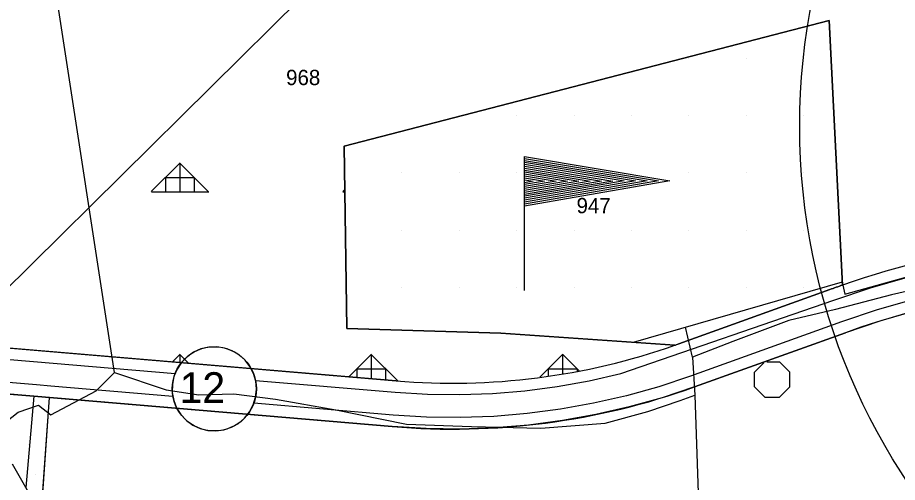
# Model space of a CAD drawing. Extents: x 410727 to 412947, y 4463506 to 4466382.
# Drawn here: x 411101.3 to 411331.1, y 4465660.4 to 4465781.8 of the extents above; entities that cross this region are included whole.
import ezdxf

# ---------------------------------------------------------------- set-up
doc = ezdxf.new("R2010")
doc.units = 0
for name, color, linetype in [('ADAKENARI', 7, 'Continuous'), ('KALDIRIM', 7, 'Continuous'), ('KDS_PARSEL_NO', 7, 'Continuous'), ('KDS_PL', 7, 'Continuous'), ('LJ_SEMBOL', 7, 'Continuous'), ('LJ_ÇERÇEVE', 7, 'Continuous'), ('PL_AYA_ORMAN', 7, 'Continuous'), ('PL_AYA_PARK_DINLENME', 7, 'Continuous'), ('PL_KA_TARIM_DIGER', 7, 'Continuous'), ('PL_SPOR', 7, 'Continuous'), ('sm_yol_beyaz', 7, 'Continuous'), ('sm_yol_genisligi', 7, 'Continuous'), ('TR_ORMAN', 7, 'Continuous'), ('TR_PARKALANI', 7, 'Continuous'), ('TR_SPOR', 7, 'Continuous'), ('TR_TARIMALANI', 7, 'Continuous'), ('Yerlesime_uygunluk_sınırı', 7, 'Continuous')]:
    doc.layers.add(name, color=color, linetype=linetype)

msp = doc.modelspace()

# ---------------------------------------------------------------- linework, layer by layer
at = {"layer": 'ADAKENARI'}
for p, q in [((411313.23, 4465781.05), (411186.63, 4465748.25)), ((411313.23, 4465781.05), (411316.74, 4465711.91)), ((411186.63, 4465748.25), (411187.26, 4465700.58)), ((411313.48, 4465710.76), (411274.04, 4465696.59)), ((411200.14, 4465686.91), (411040.78, 4465700.4)), ((411187.26, 4465700.58), (411227.54, 4465699.31)), ((411227.54, 4465699.31), (411272.97, 4465696.21)), ((411278.1, 4465685.3), (411317.54, 4465699.47)), ((411063.08, 4465686.47), (411105.53, 4465682.88)), ((411105.53, 4465682.88), (411109.68, 4465682.53)), ((411106.96, 4465644.62), (411109.68, 4465682.53)), ((411109.68, 4465682.53), (411199.13, 4465674.95))]:
    msp.add_line(p, q, dxfattribs=at)
for centre, radius, start, end in [((411398.47, 4465474.33), 251.25, 87.2905, 108.9831), ((411398.47, 4465474.33), 239.25, 77.2133, 109.7719), ((411398.47, 4465474.33), 251.25, 108.9831, 109.7719), ((411214.9, 4465861.12), 174.84, 289.3989, 289.7719), ((411214.9, 4465861.12), 174.84, 265.1582, 289.3989), ((411214.9, 4465861.12), 186.84, 265.1582, 289.7719)]:
    msp.add_arc(centre, radius, start, end, dxfattribs=at)
at = {"layer": 'KALDIRIM'}
msp.add_line((411258.83, 4465688.79), (411314.49, 4465707.94), dxfattribs=at)
for points in [[(411314.49, 4465707.94), (411324.04, 4465711.16), (411333.71, 4465713.98)], [(411335.28, 4465708.19), (411325.84, 4465705.43), (411316.52, 4465702.29), (411277.09, 4465688.12), (411268.76, 4465685.35), (411260.31, 4465682.98), (411251.76, 4465681.02), (411243.12, 4465679.46), (411234.43, 4465678.32), (411225.68, 4465677.6), (411216.91, 4465677.29), (411208.14, 4465677.41), (411199.38, 4465677.94), (411163.01, 4465681.02)], [(410789.95, 4465702), (410815.7, 4465699.61), (410852.1, 4465692.73), (410854.34, 4465692.33), (410856.59, 4465691.97), (410858.85, 4465691.64), (410861.1, 4465691.36), (410863.37, 4465691.12), (410865.64, 4465690.91), (410867.91, 4465690.75), (410870.18, 4465690.62), (410872.45, 4465690.54), (410874.71, 4465690.49), (410876.97, 4465690.49), (410879.24, 4465690.52), (410881.5, 4465690.6), (410883.76, 4465690.71), (410886.02, 4465690.86), (410888.27, 4465691.06), (410955.64, 4465697.4), (411003.29, 4465697.4), (411040.66, 4465697.4), (411142.43, 4465688.78)], [(411141.86, 4465682.81), (411109.97, 4465685.51), (411106.28, 4465685.83), (411063.54, 4465689.45)], [(411163.46, 4465687), (411199.89, 4465683.92), (411208.36, 4465683.4), (411216.85, 4465683.29), (411225.33, 4465683.59), (411233.79, 4465684.29), (411242.2, 4465685.39), (411250.56, 4465686.89), (411258.83, 4465688.79)]]:
    msp.add_lwpolyline(points, dxfattribs=at)
at = {"layer": 'KDS_PL'}
for p, q in [((411126.65, 4465689.06), (411111.15, 4465789.99)), ((411186.63, 4465748.25), (411313.23, 4465781.05)), ((411313.23, 4465781.05), (411316.7, 4465712.69)), ((411187.26, 4465700.58), (411186.63, 4465748.25)), ((411317.33, 4465709.57), (411341.21, 4465716.18)), ((411316.7, 4465712.69), (411262.1, 4465696.95)), ((411316.7, 4465712.69), (411317.33, 4465709.57)), ((411348.46, 4465713.65), (411329.56, 4465709.38)), ((411329.56, 4465709.38), (411314.94, 4465705.51)), ((411314.94, 4465705.51), (411302.74, 4465702.66)), ((411302.74, 4465702.66), (411288.12, 4465697.16)), ((411227.54, 4465699.31), (411187.26, 4465700.58)), ((411262.1, 4465696.95), (411227.54, 4465699.31)), ((411277.55, 4465693.09), (411275.75, 4465700.89)), ((411288.12, 4465697.16), (411277.55, 4465693.09)), ((411277.55, 4465693.09), (411278.16, 4465683.12)), ((411121.86, 4465684.27), (411126.65, 4465689.06)), ((411126.65, 4465689.06), (411140.12, 4465684.56)), ((411109.98, 4465678.03), (411121.86, 4465684.27)), ((411140.12, 4465684.56), (411148.67, 4465683.25)), ((411148.67, 4465683.25), (411157.8, 4465683.54)), ((411157.8, 4465683.54), (411168.67, 4465682.09)), ((411274.32, 4465681.8), (411278.16, 4465683.12)), ((411278.16, 4465683.12), (411279.18, 4465654.41)), ((411101.43, 4465678.75), (411106.79, 4465680.5)), ((411106.79, 4465680.5), (411109.98, 4465678.03)), ((411168.67, 4465682.09), (411184.47, 4465679.33)), ((411265.92, 4465678.9), (411274.32, 4465681.8)), ((411093.75, 4465672.66), (411101.43, 4465678.75)), ((411184.47, 4465679.33), (411202.88, 4465675.56)), ((411254.76, 4465675.85), (411265.92, 4465678.9)), ((411237.95, 4465674.54), (411254.76, 4465675.85)), ((411202.88, 4465675.56), (411219.83, 4465674.98)), ((411219.83, 4465674.98), (411237.95, 4465674.54)), ((411104.18, 4465657.84), (411099.98, 4465665.1))]:
    msp.add_line(p, q, dxfattribs=at)
at = {"layer": 'LJ_SEMBOL'}
msp.add_line((411233.7, 4465710.53), (411233.7, 4465745.53), dxfattribs=at)
msp.add_line((411233.7, 4465710.53), (411233.7, 4465745.53), dxfattribs=at)
msp.add_line((411233.7, 4465710.53), (411233.7, 4465745.53), dxfattribs=at)
for points in [[(411233.7, 4465745.53), (411271.65, 4465739.15), (411233.7, 4465732.57)], [(411233.7, 4465745.53), (411271.65, 4465739.15), (411233.7, 4465732.57)], [(411233.7, 4465745.53), (411271.65, 4465739.15), (411233.7, 4465732.57)], [(411233.7, 4465745.02), (411268.68, 4465739.14), (411233.7, 4465733.08)], [(411233.7, 4465745.02), (411268.68, 4465739.14), (411233.7, 4465733.08)], [(411233.7, 4465745.02), (411268.68, 4465739.14), (411233.7, 4465733.08)], [(411233.7, 4465744.51), (411265.71, 4465739.13), (411233.7, 4465733.59)], [(411233.7, 4465744.51), (411265.71, 4465739.13), (411233.7, 4465733.59)], [(411233.7, 4465744.51), (411265.71, 4465739.13), (411233.7, 4465733.59)], [(411233.7, 4465744), (411262.73, 4465739.12), (411233.7, 4465734.1)], [(411233.7, 4465744), (411262.73, 4465739.12), (411233.7, 4465734.1)], [(411233.7, 4465744), (411262.73, 4465739.12), (411233.7, 4465734.1)], [(411233.7, 4465743.5), (411259.76, 4465739.12), (411233.7, 4465734.6)], [(411233.7, 4465743.5), (411259.76, 4465739.12), (411233.7, 4465734.6)], [(411233.7, 4465743.5), (411259.76, 4465739.12), (411233.7, 4465734.6)], [(411233.7, 4465742.99), (411256.79, 4465739.11), (411233.7, 4465735.11)], [(411233.7, 4465742.99), (411256.79, 4465739.11), (411233.7, 4465735.11)], [(411233.7, 4465742.99), (411256.79, 4465739.11), (411233.7, 4465735.11)], [(411233.7, 4465742.48), (411253.82, 4465739.1), (411233.7, 4465735.62)], [(411233.7, 4465742.48), (411253.82, 4465739.1), (411233.7, 4465735.62)], [(411233.7, 4465742.48), (411253.82, 4465739.1), (411233.7, 4465735.62)], [(411233.7, 4465741.98), (411250.85, 4465739.09), (411233.7, 4465736.13)], [(411233.7, 4465741.98), (411250.85, 4465739.09), (411233.7, 4465736.13)], [(411233.7, 4465741.98), (411250.85, 4465739.09), (411233.7, 4465736.13)], [(411233.7, 4465741.47), (411247.87, 4465739.09), (411233.7, 4465736.63)], [(411233.7, 4465741.47), (411247.87, 4465739.09), (411233.7, 4465736.63)], [(411233.7, 4465741.47), (411247.87, 4465739.09), (411233.7, 4465736.63)], [(411233.7, 4465740.96), (411244.9, 4465739.08), (411233.7, 4465737.14)], [(411233.7, 4465740.96), (411244.9, 4465739.08), (411233.7, 4465737.14)], [(411233.7, 4465740.96), (411244.9, 4465739.08), (411233.7, 4465737.14)], [(411233.7, 4465740.46), (411241.93, 4465739.07), (411233.7, 4465737.65)], [(411233.7, 4465740.46), (411241.93, 4465739.07), (411233.7, 4465737.65)], [(411233.7, 4465740.46), (411241.93, 4465739.07), (411233.7, 4465737.65)], [(411233.7, 4465739.95), (411238.96, 4465739.07), (411233.7, 4465738.16)], [(411233.7, 4465739.95), (411238.96, 4465739.07), (411233.7, 4465738.16)], [(411233.7, 4465739.95), (411238.96, 4465739.07), (411233.7, 4465738.16)], [(411233.7, 4465739.44), (411235.98, 4465739.06), (411233.7, 4465738.66)], [(411233.7, 4465739.44), (411235.98, 4465739.06), (411233.7, 4465738.66)], [(411233.7, 4465739.44), (411235.98, 4465739.06), (411233.7, 4465738.66)]]:
    msp.add_lwpolyline(points, dxfattribs=at)
at = {"layer": 'LJ_ÇERÇEVE'}
msp.add_circle((411473.17, 4465753.45), 167.6, dxfattribs=at)
at = {"layer": 'PL_AYA_ORMAN'}
for points in [[(411272.97, 4465696.21), (411272.97, 4465696.21), (411227.54, 4465699.31), (411187.26, 4465700.58), (411186.63, 4465748.25), (411313.23, 4465781.05), (411316.74, 4465711.91)], [(410887.99, 4465694.04), (410955.49, 4465700.4), (411040.78, 4465700.4), (411200.14, 4465686.91)]]:
    msp.add_lwpolyline(points, dxfattribs=at)
for centre, radius, start, end in [((411398.47, 4465474.33), 251.25, 87.2906, 108.9831), ((411398.47, 4465474.33), 251.25, 108.9831, 108.9832), ((411214.9, 4465861.12), 174.84, 265.1582, 289.3989)]:
    msp.add_arc(centre, radius, start, end, dxfattribs=at)
at = {"layer": 'PL_AYA_PARK_DINLENME'}
msp.add_lwpolyline([(411094.14, 4465609.66), (411105.43, 4465627.61), (411109.63, 4465634.49), (411105.8, 4465640.38), (411106.96, 4465644.62), (411109.68, 4465682.53), (411105.53, 4465682.88), (411063.08, 4465686.47)], dxfattribs=at)
at = {"layer": 'PL_KA_TARIM_DIGER'}
msp.add_lwpolyline([(411336.06, 4465705.29), (411326.74, 4465702.57), (411317.54, 4465699.47), (411278.1, 4465685.3), (411269.64, 4465682.48), (411261.05, 4465680.07), (411252.36, 4465678.08), (411243.59, 4465676.5), (411234.74, 4465675.34), (411225.86, 4465674.6), (411216.95, 4465674.29), (411208.03, 4465674.41), (411199.13, 4465674.95), (411105.53, 4465682.88), (411103.5, 4465658.98)], dxfattribs=at)
at = {"layer": 'PL_SPOR'}
msp.add_lwpolyline([(411186.63, 4465748.25), (411187.26, 4465700.58), (411227.54, 4465699.31), (411272.97, 4465696.21), (411273.1, 4465696.25), (411273.24, 4465696.3), (411273.37, 4465696.35), (411273.51, 4465696.4), (411273.64, 4465696.45), (411273.77, 4465696.49), (411273.91, 4465696.54), (411274.04, 4465696.59), (411313.48, 4465710.76), (411313.88, 4465710.91), (411314.29, 4465711.06), (411314.7, 4465711.2), (411315.11, 4465711.34), (411315.51, 4465711.49), (411315.92, 4465711.63), (411316.33, 4465711.77), (411316.74, 4465711.91), (411313.23, 4465781.05), (411186.63, 4465748.25)], dxfattribs=at)
at = {"layer": 'sm_yol_beyaz'}
msp.add_lwpolyline([(411163.68, 4465684.69), (411163.5, 4465686.77), (411162.93, 4465688.79), (411161.99, 4465690.66), (411160.72, 4465692.31), (411159.15, 4465693.7), (411157.35, 4465694.76), (411155.38, 4465695.46), (411153.31, 4465695.78), (411151.22, 4465695.7), (411149.18, 4465695.23), (411147.27, 4465694.38), (411145.56, 4465693.18), (411144.1, 4465691.68), (411142.95, 4465689.94), (411142.16, 4465688), (411141.74, 4465685.95), (411141.72, 4465683.86), (411142.09, 4465681.8), (411142.85, 4465679.86), (411143.97, 4465678.08), (411145.39, 4465676.56), (411147.09, 4465675.33), (411148.98, 4465674.44), (411151.01, 4465673.93), (411153.09, 4465673.81), (411155.17, 4465674.08), (411157.15, 4465674.75), (411158.97, 4465675.78), (411160.57, 4465677.13), (411161.87, 4465678.76), (411162.85, 4465680.61), (411163.46, 4465682.61), (411163.68, 4465684.69)], dxfattribs=at)
at = {"layer": 'sm_yol_genisligi'}
msp.add_circle((411152.68, 4465684.8), 11, dxfattribs=at)
at = {"layer": 'TR_ORMAN'}
for p, q in [((411136.24, 4465736.35), (411143.74, 4465743.84)), ((411151.15, 4465736.31), (411143.65, 4465743.81)), ((411143.75, 4465736.29), (411143.75, 4465743.79)), ((411140, 4465736.29), (411140, 4465740.04)), ((411140, 4465740.04), (411147.5, 4465740.04)), ((411147.5, 4465736.29), (411147.5, 4465740.04)), ((411136.25, 4465736.29), (411151.25, 4465736.29)), ((411186.24, 4465736.35), (411186.78, 4465736.89)), ((411186.25, 4465736.29), (411186.79, 4465736.29)), ((411141.74, 4465691.85), (411143.74, 4465693.85)), ((411141.74, 4465691.85), (411143.74, 4465693.85)), ((411145.98, 4465691.49), (411143.68, 4465693.79)), ((411145.98, 4465691.49), (411143.68, 4465693.79)), ((411143.75, 4465691.68), (411143.75, 4465693.79)), ((411143.75, 4465691.68), (411143.75, 4465693.79)), ((411187.83, 4465687.95), (411193.74, 4465693.86)), ((411187.83, 4465687.95), (411193.74, 4465693.86)), ((411200.59, 4465686.88), (411193.67, 4465693.79)), ((411200.59, 4465686.88), (411193.67, 4465693.79)), ((411193.75, 4465687.45), (411193.75, 4465693.79)), ((411193.75, 4465687.45), (411193.75, 4465693.79)), ((411237.7, 4465687.82), (411243.74, 4465693.87)), ((411237.7, 4465687.82), (411243.74, 4465693.87)), ((411247.99, 4465689.47), (411243.67, 4465693.79)), ((411247.99, 4465689.47), (411243.67, 4465693.79)), ((411243.75, 4465688.72), (411243.75, 4465693.79)), ((411243.75, 4465688.72), (411243.75, 4465693.79)), ((411190, 4465687.76), (411190, 4465690.04)), ((411190, 4465690.04), (411197.5, 4465690.04)), ((411190, 4465687.76), (411190, 4465690.04)), ((411190, 4465690.04), (411197.5, 4465690.04)), ((411197.5, 4465687.13), (411197.5, 4465690.04)), ((411197.5, 4465687.13), (411197.5, 4465690.04)), ((411240, 4465688.12), (411240, 4465690.04)), ((411240, 4465690.04), (411247.5, 4465690.04)), ((411240, 4465688.12), (411240, 4465690.04)), ((411240, 4465690.04), (411247.5, 4465690.04)), ((411247.5, 4465689.38), (411247.5, 4465690.04)), ((411247.5, 4465689.38), (411247.5, 4465690.04))]:
    msp.add_line(p, q, dxfattribs=at)
at = {"layer": 'TR_PARKALANI'}
for p, q in [((411102.17, 4465679.03), (411102.17, 4465679.03)), ((411102.17, 4465679.03), (411102.17, 4465679.03)), ((411104.29, 4465670.18), (411104.29, 4465670.18)), ((411104.29, 4465670.18), (411104.29, 4465670.18)), ((411106.05, 4465662.49), (411106.05, 4465662.49))]:
    msp.add_line(p, q, dxfattribs=at)
at = {"layer": 'TR_SPOR'}
for p, q in [((411276.63, 4465771.21), (411276.63, 4465771.21)), ((411291.63, 4465771.21), (411291.63, 4465771.21)), ((411306.63, 4465771.21), (411306.63, 4465771.21)), ((411231.63, 4465756.21), (411231.63, 4465756.21)), ((411246.63, 4465756.21), (411246.63, 4465756.21)), ((411261.63, 4465756.21), (411261.63, 4465756.21)), ((411276.63, 4465756.21), (411276.63, 4465756.21)), ((411291.63, 4465756.21), (411291.63, 4465756.21)), ((411306.63, 4465756.21), (411306.63, 4465756.21)), ((411201.63, 4465741.21), (411201.63, 4465741.21)), ((411216.63, 4465741.21), (411216.63, 4465741.21)), ((411231.63, 4465741.21), (411231.63, 4465741.21)), ((411246.63, 4465741.21), (411246.63, 4465741.21)), ((411261.63, 4465741.21), (411261.63, 4465741.21)), ((411276.63, 4465741.21), (411276.63, 4465741.21)), ((411291.63, 4465741.21), (411291.63, 4465741.21)), ((411306.63, 4465741.21), (411306.63, 4465741.21)), ((411201.63, 4465726.21), (411201.63, 4465726.21)), ((411216.63, 4465726.21), (411216.63, 4465726.21)), ((411231.63, 4465726.21), (411231.63, 4465726.21)), ((411246.63, 4465726.21), (411246.63, 4465726.21)), ((411261.63, 4465726.21), (411261.63, 4465726.21)), ((411276.63, 4465726.21), (411276.63, 4465726.21)), ((411291.63, 4465726.21), (411291.63, 4465726.21)), ((411306.63, 4465726.21), (411306.63, 4465726.21)), ((411201.63, 4465711.21), (411201.63, 4465711.21)), ((411216.63, 4465711.21), (411216.63, 4465711.21)), ((411231.63, 4465711.21), (411231.63, 4465711.21)), ((411246.63, 4465711.21), (411246.63, 4465711.21)), ((411261.63, 4465711.21), (411261.63, 4465711.21)), ((411276.63, 4465711.21), (411276.63, 4465711.21)), ((411291.63, 4465711.21), (411291.63, 4465711.21)), ((411306.63, 4465711.21), (411306.63, 4465711.21))]:
    msp.add_line(p, q, dxfattribs=at)
at = {"layer": 'TR_TARIMALANI'}
for p, q in [((411296.97, 4465691.9), (411300.29, 4465691.9)), ((411296.97, 4465691.9), (411300.29, 4465691.9)), ((411303, 4465689.19), (411300.29, 4465691.89)), ((411303, 4465689.19), (411300.29, 4465691.89)), ((411293.75, 4465689.19), (411296.17, 4465691.61)), ((411293.75, 4465689.19), (411296.17, 4465691.61)), ((411293.75, 4465685.36), (411293.75, 4465689.19)), ((411293.75, 4465685.36), (411293.75, 4465689.19)), ((411303, 4465685.36), (411303, 4465689.19)), ((411303, 4465685.36), (411303, 4465689.19)), ((411296.46, 4465682.65), (411293.75, 4465685.35)), ((411296.46, 4465682.65), (411293.75, 4465685.35)), ((411300.29, 4465682.65), (411302.99, 4465685.35)), ((411300.29, 4465682.65), (411302.99, 4465685.35)), ((411296.46, 4465682.65), (411300.29, 4465682.65)), ((411296.46, 4465682.65), (411300.29, 4465682.65))]:
    msp.add_line(p, q, dxfattribs=at)
at = {"layer": 'Yerlesime_uygunluk_sınırı'}
msp.add_lwpolyline([(411198.74, 4465810.19), (411081.53, 4465694.24), (411105.16, 4465639.97), (411025.76, 4465514.96), (411000.79, 4465488.66), (410885.69, 4465447.82), (410793.52, 4465421.54)], dxfattribs=at)

# ---------------------------------------------------------------- texts
at = {"layer": 'KDS_PARSEL_NO'}
for s, p in [('968', (411171.44, 4465764.17)), ('947', (411247.29, 4465730.69))]:
    msp.add_text(s, height=4, dxfattribs=at).set_placement(p)
at = {"layer": 'sm_yol_genisligi'}
msp.add_text('12', height=8, dxfattribs=at).set_placement((411143.62, 4465681.14))

doc.saveas('drawing.dxf')
